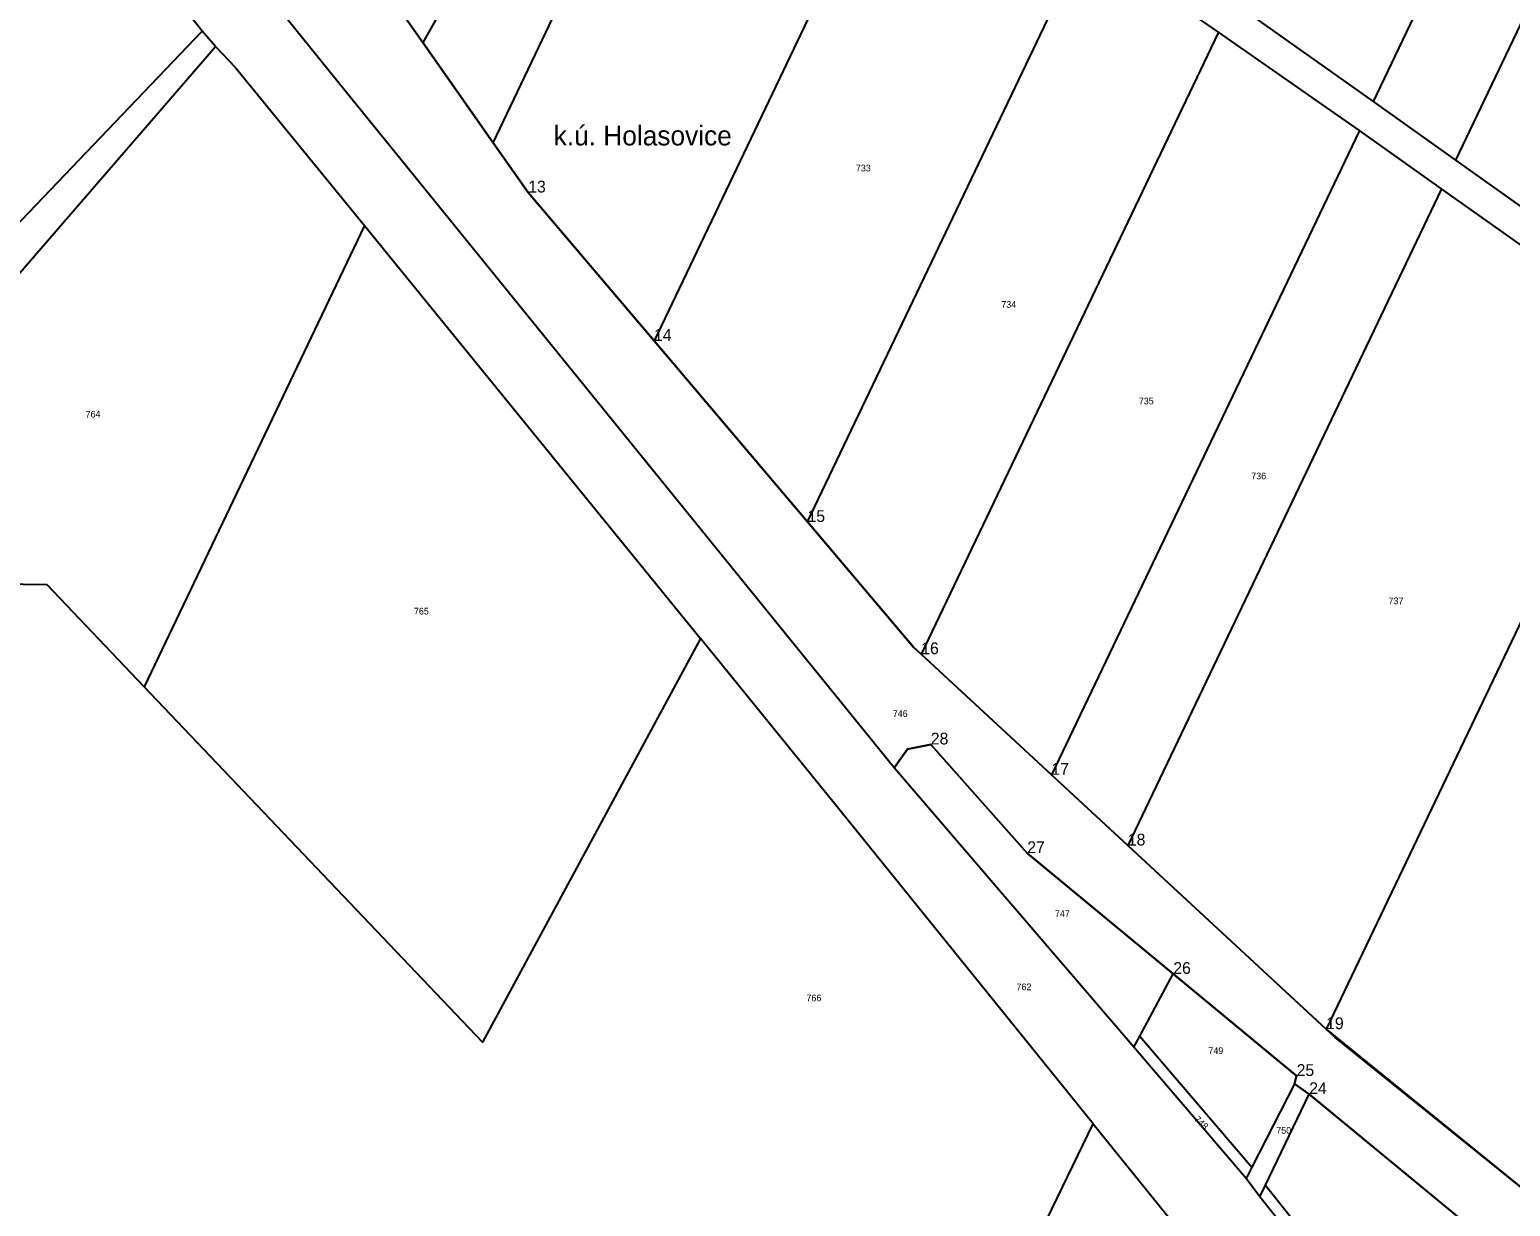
# Model space of a CAD drawing. Extents: x -504601 to -503665, y -1079870 to -1078626.
# Drawn here: x -504268.5 to -503891.4, y -1079448.1 to -1079148.4 of the extents above; entities that cross this region are included whole.
import ezdxf

# ---------------------------------------------------------------- set-up
doc = ezdxf.new("R2010")
doc.units = 0
for name, color, linetype in [('Hranice parcel', 7, 'Continuous'), ('Parcelní čísla', 7, 'Continuous'), ('Polygon ku', 7, 'Continuous'), ('Vrstva 31', 7, 'Continuous'), ('Vrstva 32', 7, 'Continuous'), ('Vrstva 54', 7, 'Continuous')]:
    doc.layers.add(name, color=color, linetype=linetype)

msp = doc.modelspace()

# ---------------------------------------------------------------- linework, layer by layer
at = {"layer": 'Hranice parcel'}
for p, q in [((-504150.39, -1079177.22), (-504094.24, -1079059.5)), ((-504045.55, -1079093.99), (-504109.47, -1079227.67)), ((-504168.33, -1079151.66), (-504187.04, -1079125.02)), ((-504070.38, -1079273.8), (-503999.6, -1079125.68)), ((-503965.74, -1079149.03), (-503999.6, -1079125.68)), ((-503960.91, -1079142.29), (-503926.36, -1079166.74)), ((-504221.12, -1079152.74), (-504224.49, -1079148.81)), ((-503965.74, -1079149.03), (-504041.43, -1079307.47)), ((-503929.86, -1079174.07), (-503965.74, -1079149.03)), ((-504150.39, -1079177.22), (-504168.33, -1079151.66)), ((-503926.36, -1079166.74), (-503905.42, -1079181.64)), ((-503929.86, -1079174.07), (-504008.27, -1079338.19)), ((-503908.92, -1079188.96), (-503929.86, -1079174.07)), ((-503905.42, -1079181.64), (-503850.5, -1079220.7)), ((-503908.92, -1079188.96), (-503988.82, -1079356.2)), ((-503854.56, -1079227.62), (-503908.92, -1079188.96)), ((-504183.22, -1079198.33), (-504239.26, -1079315.79)), ((-504183.22, -1079198.33), (-504097.67, -1079303.47)), ((-504070.38, -1079273.8), (-504109.47, -1079227.67)), ((-503854.56, -1079227.62), (-503938.33, -1079402.97)), ((-504008.27, -1079338.19), (-504041.43, -1079307.47)), ((-503987.33, -1079407.59), (-504048.32, -1079336.41)), ((-503988.82, -1079356.2), (-504008.27, -1079338.19)), ((-503938.33, -1079402.97), (-503988.82, -1079356.2)), ((-503985.81, -1079404.77), (-503977.25, -1079388.9)), ((-503987.33, -1079407.59), (-503985.81, -1079404.77)), ((-503985.81, -1079404.77), (-503957.24, -1079438.12)), ((-503958.71, -1079441.01), (-503987.33, -1079407.59)), ((-503946.4, -1079416.88), (-503957.24, -1079438.12)), ((-503953.77, -1079442.68), (-503942.64, -1079419.51)), ((-503946.4, -1079416.88), (-503942.64, -1079419.51)), ((-503942.64, -1079419.51), (-503895.86, -1079458.07)), ((-503997.67, -1079427.08), (-503950.22, -1079485.75)), ((-503957.24, -1079438.12), (-503958.71, -1079441.01)), ((-503955.21, -1079445.68), (-503958.71, -1079441.01)), ((-503955.21, -1079445.68), (-503953.77, -1079442.68)), ((-503953.77, -1079442.68), (-503912.97, -1079493.9))]:
    msp.add_line(p, q, dxfattribs=at)
for points in [[(-503787.07, -1078875.01), (-503845.26, -1078996.89), (-503926.36, -1079166.74)], [(-503758.93, -1078875.01), (-503827.49, -1079018.52), (-503905.42, -1079181.64)], [(-504048.32, -1079336.41), (-504164.13, -1079193.65), (-504189.98, -1079161.66), (-504303.4, -1079021.3), (-504338.19, -1078978.95)], [(-504113.31, -1079045.35), (-504120.83, -1079067.9), (-504168.33, -1079151.66)], [(-504224.49, -1079148.81), (-504231.2, -1079140.26), (-504237.3, -1079132.48)], [(-504343.18, -1079281.39), (-504285.23, -1079212.2), (-504231.96, -1079156.61), (-504224.49, -1079148.81)], [(-504331.73, -1079288.88), (-504307.23, -1079252.28), (-504221.12, -1079152.74)], [(-504221.12, -1079152.74), (-504216.11, -1079157.97), (-504183.22, -1079198.33)], [(-504109.47, -1079227.67), (-504141.49, -1079189.89), (-504150.39, -1079177.22)], [(-504041.43, -1079307.47), (-504043.38, -1079305.66), (-504070.38, -1079273.8)], [(-504239.26, -1079315.79), (-504263.96, -1079289.85), (-504331.73, -1079288.88)], [(-504097.67, -1079303.47), (-504153.14, -1079406.27), (-504239.26, -1079315.79)], [(-503997.67, -1079427.08), (-504063.57, -1079345.38), (-504097.67, -1079303.47)], [(-504048.32, -1079336.41), (-504044.97, -1079331.7), (-504038.99, -1079330.47), (-504014.44, -1079358.14), (-503977.25, -1079388.9)], [(-503977.25, -1079388.9), (-503945.84, -1079414.89), (-503946.4, -1079416.88)], [(-503888.76, -1079443.21), (-503936.1, -1079405.04), (-503938.33, -1079402.97)], [(-504131.58, -1079709.87), (-504110.18, -1079659.69), (-504032.95, -1079500.02), (-503997.67, -1079427.08)], [(-503697.84, -1079765.64), (-503779.17, -1079666.7), (-503806.76, -1079632.06), (-503843.08, -1079586.46), (-503955.21, -1079445.68)]]:
    msp.add_lwpolyline(points, dxfattribs=at)
at = {"layer": 'Vrstva 31'}
for p, q in [((-504141.49, -1079189.89), (-504141.49, -1079189.89)), ((-504109.47, -1079227.67), (-504109.47, -1079227.67)), ((-504070.38, -1079273.8), (-504070.38, -1079273.8)), ((-504041.43, -1079307.47), (-504041.43, -1079307.47)), ((-504038.99, -1079330.47), (-504038.99, -1079330.47)), ((-504008.27, -1079338.19), (-504008.27, -1079338.19)), ((-503988.82, -1079356.2), (-503988.82, -1079356.2)), ((-504014.44, -1079358.14), (-504014.44, -1079358.14)), ((-503977.25, -1079388.9), (-503977.25, -1079388.9)), ((-503938.33, -1079402.97), (-503938.33, -1079402.97)), ((-503945.84, -1079414.89), (-503945.84, -1079414.89)), ((-503942.64, -1079419.51), (-503942.64, -1079419.51))]:
    msp.add_line(p, q, dxfattribs=at)
at = {"layer": 'Vrstva 54'}
for points in [[(-503867.31, -1079481.6), (-503895.86, -1079458.07), (-503942.64, -1079419.51), (-503946.4, -1079416.88), (-503945.84, -1079414.89), (-503977.25, -1079388.9), (-504014.44, -1079358.14), (-504038.99, -1079330.47), (-504044.97, -1079331.7), (-504048.32, -1079336.41), (-504164.13, -1079193.65), (-504189.98, -1079161.66), (-504303.4, -1079021.3)], [(-504259.1, -1079048.24), (-504191.97, -1079119.35), (-504187.04, -1079125.02), (-504168.33, -1079151.66), (-504150.39, -1079177.22), (-504141.49, -1079189.89), (-504109.47, -1079227.67), (-504070.38, -1079273.8), (-504043.38, -1079305.66), (-504041.43, -1079307.47), (-504008.27, -1079338.19), (-503988.82, -1079356.2), (-503938.33, -1079402.97), (-503888.76, -1079443.21), (-503860.04, -1079466.37)]]:
    msp.add_lwpolyline(points, dxfattribs=at)

# ---------------------------------------------------------------- texts
at = {"layer": 'Parcelní čísla'}
for s, p in [('733', (-504058.07, -1079184.51)), ('734', (-504021.04, -1079219.25)), ('735', (-503986.03, -1079243.85)), ('764', (-504254.21, -1079247.2)), ('736', (-503957.41, -1079262.93)), ('765', (-504170.6, -1079297.36)), ('737', (-503922.44, -1079294.74)), ('746', (-504048.68, -1079323.43)), ('747', (-504007.38, -1079374.37)), ('766', (-504070.66, -1079395.86)), ('762', (-504017.17, -1079393.05)), ('762', (-504017.17, -1079393.05)), ('749', (-503968.32, -1079409.3)), ('750', (-503951.04, -1079429.6))]:
    msp.add_text(s, height=1.7, dxfattribs=at).set_placement(p)
msp.add_text('748', height=1.7, rotation=316, dxfattribs=at).set_placement((-503972.06, -1079426.09))
at = {"layer": 'Polygon ku'}
msp.add_text('k.ú. Holasovice', height=5, dxfattribs=at).set_placement((-504135.01, -1079177.9))
at = {"layer": 'Vrstva 32'}
for s, p in [('13', (-504141.49, -1079189.89)), ('14', (-504109.47, -1079227.67)), ('15', (-504070.38, -1079273.8)), ('16', (-504041.43, -1079307.47)), ('28', (-504038.99, -1079330.47)), ('17', (-504008.27, -1079338.19)), ('27', (-504014.44, -1079358.14)), ('18', (-503988.82, -1079356.2)), ('26', (-503977.25, -1079388.9)), ('19', (-503938.33, -1079402.97)), ('25', (-503945.84, -1079414.89)), ('24', (-503942.64, -1079419.51))]:
    msp.add_text(s, height=3, dxfattribs=at).set_placement(p)

doc.saveas('drawing.dxf')
